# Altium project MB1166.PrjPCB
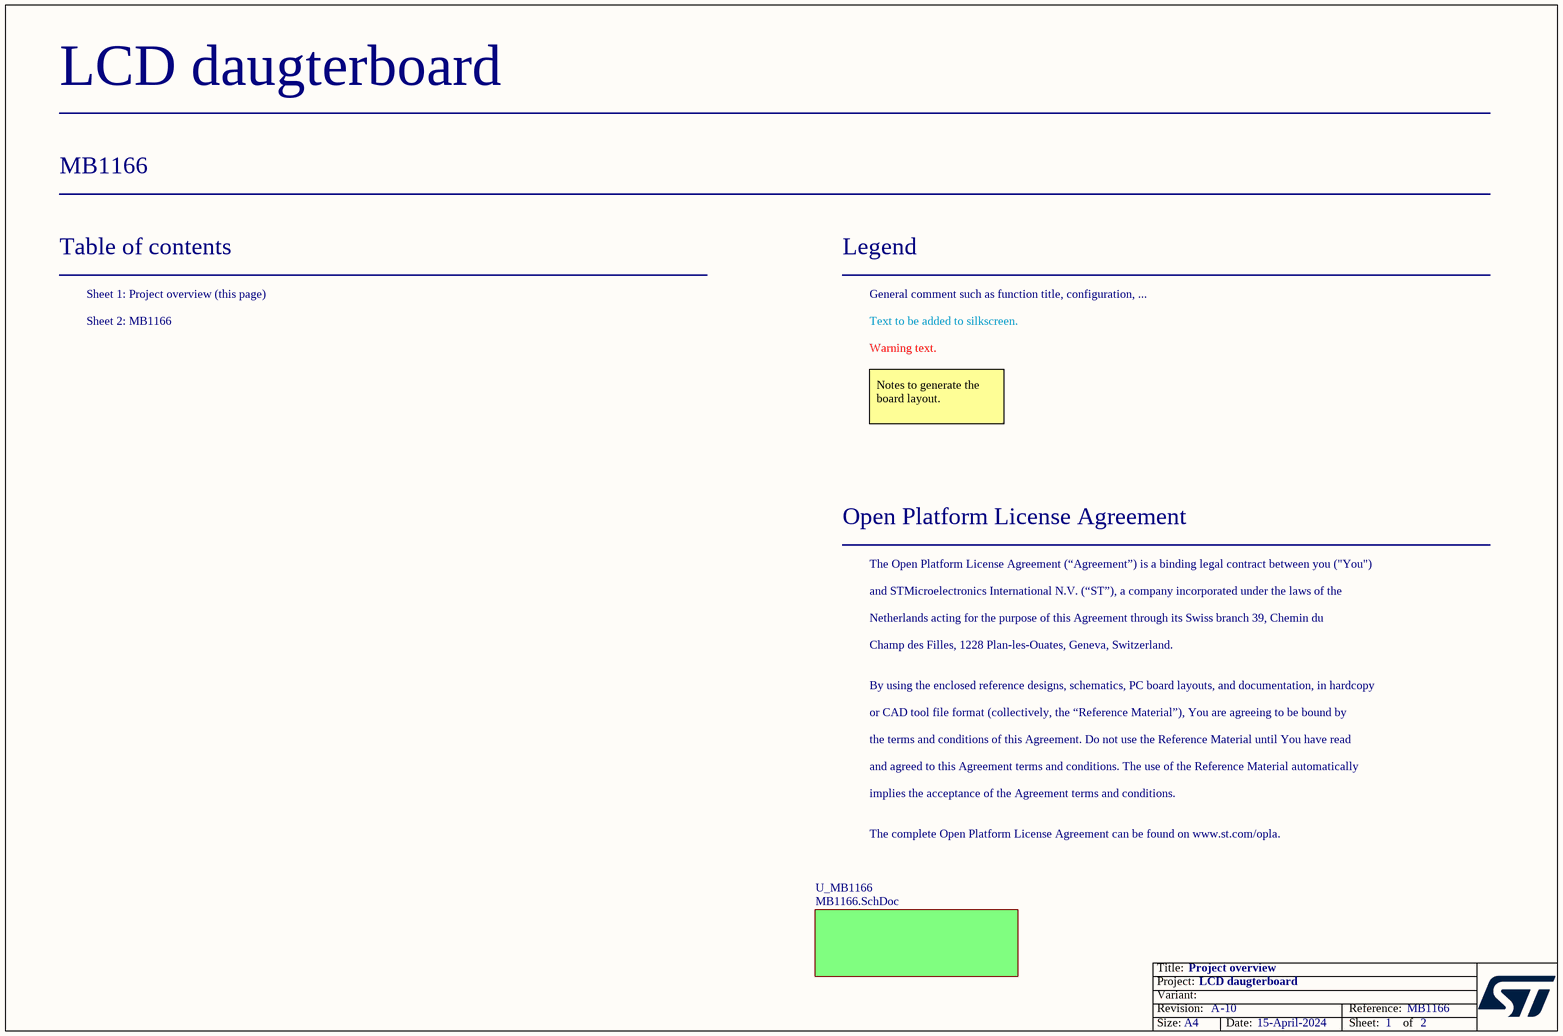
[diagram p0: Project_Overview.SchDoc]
Board_reference: MB1166; Board_PCB_revision: A; Board_name: LCD daugterboard; Board_document_date: 15-April-2024; Board_Assembly_revision: 10
2 sheets, 35 parts. Net scope: global (net labels, ports and power ports of the same name join across sheets).
Sheets:
  Project_Overview.SchDoc
    U_MB1166 = MB1166.SchDoc

## Sheet Project_Overview.SchDoc: Project overview
size A4; Date: Not used; ApprovedBy: Not used; CheckedBy: Not used; Author: Not used; CompanyName: STMicroelectronics; DrawnBy: Not used; Engineer: Not used; Organization: Not used; Address1: Not used; Address2: Not used; Address3: Not used; Address4: Not used; DocumentNumber: MB1166; Revision: Not used; SheetNumber: 1; SheetTotal: 2

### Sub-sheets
U_MB1166 = MB1166.SchDoc: no entries

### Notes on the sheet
- Table of contents
- Sheet 1: Project overview (this page)
- Legend
- General comment such as function title, configuration, ...
- Sheet 2: MB1166
- Text to be added to silkscreen.
- Warning text.
- Notes to generate the board layout.
- Open Platform License Agreement
- The Open Platform License Agreement (“Agreement”) is a binding legal contract between you ("You")
- and STMicroelectronics International N.V. (“ST”), a company incorporated under the laws of the
- Netherlands acting for the purpose of this Agreement through its Swiss branch 39, Chemin du
- Champ des Filles, 1228 Plan-les-Ouates, Geneva, Switzerland.
- By using the enclosed reference designs, schematics, PC board layouts, and documentation, in hardcopy
- or CAD tool file format (collectively, the “Reference Material”), You are agreeing to be bound by
- the terms and conditions of this Agreement. Do not use the Reference Material until You have read
- and agreed to this Agreement terms and conditions. The use of the Reference Material automatically
- implies the acceptance of the Agreement terms and conditions.
- The complete Open Platform License Agreement can be found on www.st.com/opla.

## Sheet MB1166.SchDoc: 4 inch DSI LCD board
size A4; DocumentNumber: MB1166; Revision: A.1; SheetNumber: 2; SheetTotal: 2; Project: LCD daugterboard
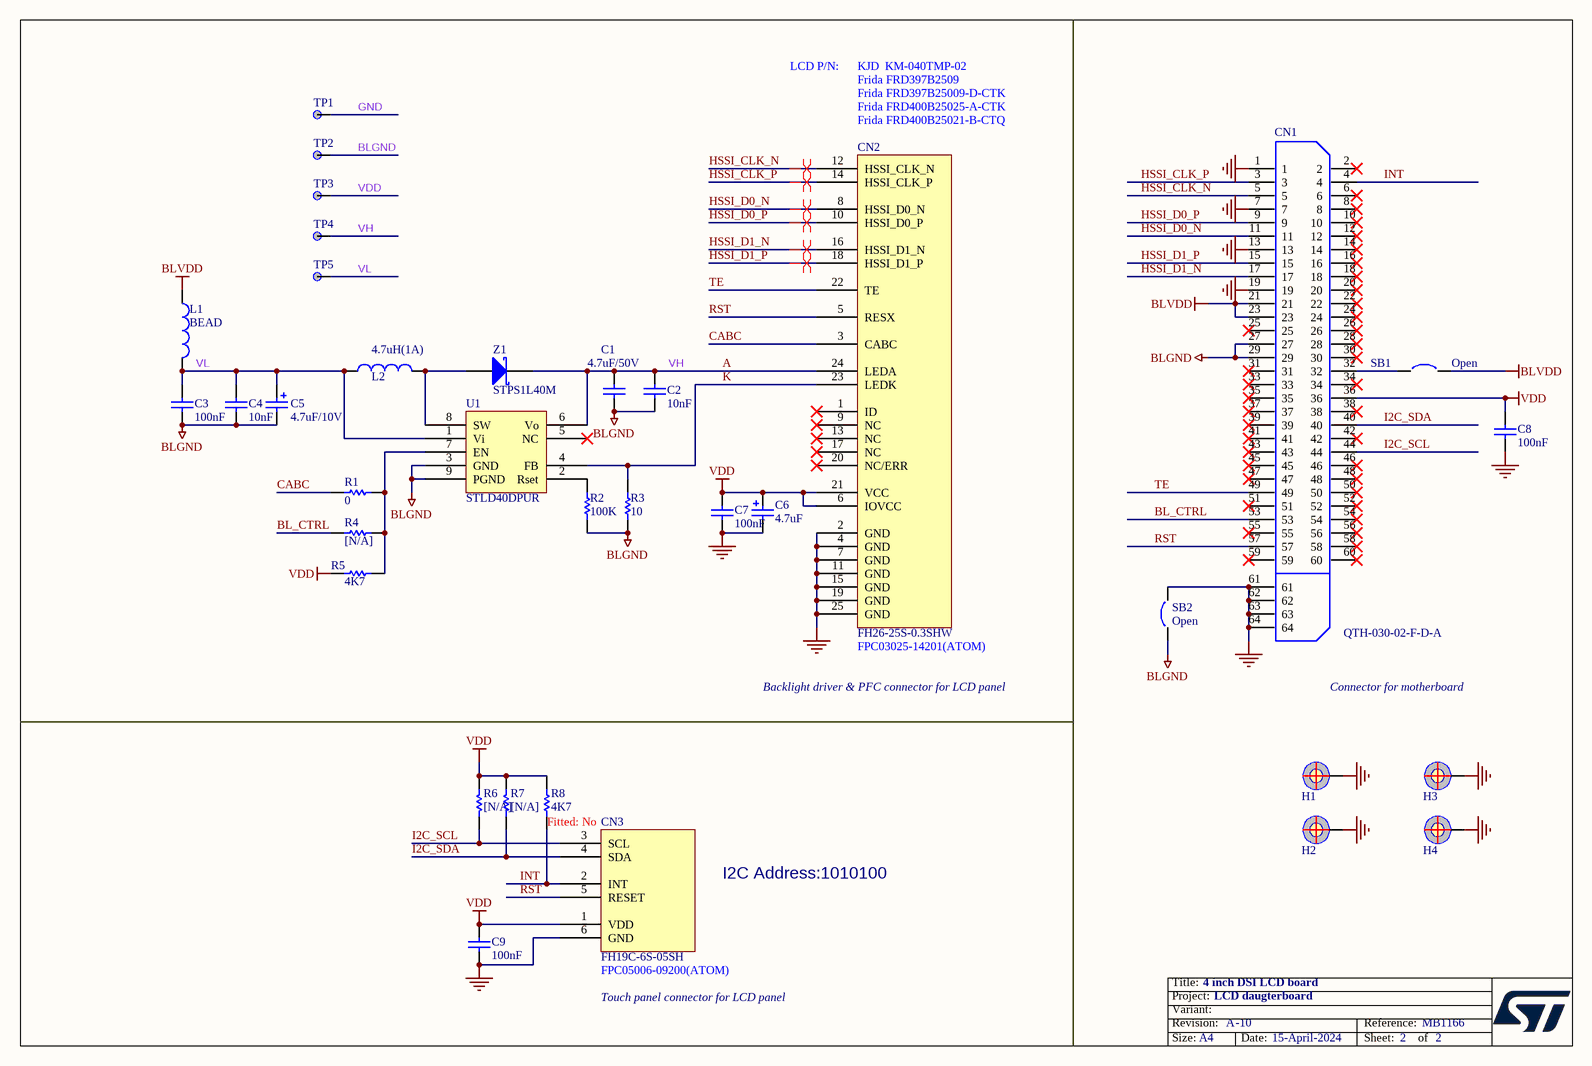
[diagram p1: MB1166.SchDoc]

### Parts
C1  4.7uF/50V  [1206C]
C2  10nF  [0603C]
C3  100nF  [0603C]
C4  10nF  [0603C]
C5  4.7uF/10V  [1206C]
C6  4.7uF  [TAN-A]
C7  100nF  [0603C]
C8  100nF  [0603C]
C9  100nF  [0603C]
CN1  QTH-030-02-F-D-A  [QTH-030-02-F-D-A]
CN2  FH26-25S-0.3SHW  [FPC25_FPC03025-1420]
CN3  FH19C-6S-05SH  [FH19C-6S-0R5Sh_FPC_CPT]
H1  POSITION HOLE  [HOLE_C9D4R5]  (value not drawn)
H2  POSITION HOLE  [HOLE_C9D4R5]  (value not drawn)
H3  POSITION HOLE  [HOLE_C9D4R5]  (value not drawn)
H4  POSITION HOLE  [HOLE_C9D4R5]  (value not drawn)
L1  BEAD  [0603L]
L2  4.7uH(1A)  [1210L]
R1  0  [0603R]
R2  100K  [0603R]
R3  10  [0603R]
R4  [N/A]  [0603R]
R5  4K7  [0603R]
R6  [N/A]  [0603R]
R7  [N/A]  [0603R]
R8  4K7  Fitted: No  [0603R]
SB1  Open  [SB_0603]
SB2  Open  [SB_0603]
TP1  (no value)  [TP]
TP2  (no value)  [TP]
TP3  (no value)  [TP]
TP4  (no value)  [TP]
TP5  (no value)  [TP]
U1  STLD40DPUR  [SON8_0R65_3X3]
Z1  STPS1L40M  [DO-216AA]

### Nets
BLGND: C1.2 C2.1 C3.1 C4.1 C5.2 CN1.27 CN1.29 R2.2 R3.1 SB2.1 TP2.1 U1.3(GND) U1.9(PGND)
BLVDD: CN1.21 CN1.23 L1.1 SB1.2
GND: C6.2 C7.1 C8.1 C9.1 CN1.1 CN1.7 CN1.13 CN1.19 CN1.61 CN1.62 CN1.63 CN1.64 CN2.2(GND) CN2.4(GND) CN2.7(GND) CN2.11(GND) CN2.15(GND) CN2.19(GND) CN2.25(GND) CN3.6(GND) H1.1 H2.1 H3.1 H4.1 SB2.2 TP1.1
VDD: C6.1 C7.2 C8.2 C9.2 CN1.36 CN2.6(IOVCC) CN2.21(VCC) CN3.1(VDD) R5.2 R6.2 R7.2 R8.1 TP3.1
A: C1.1 C2.2 CN2.24(LEDA) TP4.1 U1.6(Vo) Z1.2(K)  [also labelled VH]
BL_CTRL: CN1.53 R4.2
CABC: CN2.3(CABC) R1.2
HSSI_CLK_N: CN1.5 CN2.12(HSSI_CLK_N)
HSSI_CLK_P: CN1.3 CN2.14(HSSI_CLK_P)
HSSI_D0_N: CN1.11 CN2.8(HSSI_D0_N)
HSSI_D0_P: CN1.9 CN2.10(HSSI_D0_P)
HSSI_D1_N: CN1.17 CN2.16(HSSI_D1_N)
HSSI_D1_P: CN1.15 CN2.18(HSSI_D1_P)
I2C_SCL: CN1.44 CN3.3(SCL) R6.1
I2C_SDA: CN1.40 CN3.4(SDA) R7.1
INT: CN1.4 CN3.2(INT) R8.2
K: CN2.23(LEDK) R3.2 U1.4(FB)
RST: CN1.57 CN2.5(RESX) CN3.5(RESET)
TE: CN1.49 CN2.22(TE)
VL: C3.2 C4.2 C5.1 L1.2 L2.1 TP5.1 U1.1(Vi)
NetCN1_32: CN1.32 SB1.1
NetL2_2: L2.2 U1.8(SW) Z1.1(A)
NetR1_1: R1.1 R4.1 R5.1 U1.7(EN)
NetR2_1: R2.1 U1.2(Rset)

Not connected (* = marked no-connect by the designer): CN1 2* 6* 8* 10* 12* 14* 16* 18* 20* 22* 24* 25* 26* 28* 30* 31* 33* 34* 35* 37* 38* 39* 41* 42* 43* 45* 46* 47* 48* 50* 51* 52* 54* 55* 56* 58* 59* 60*; CN2 1(ID)* 9(NC)* 13(NC)* 17(NC)* 20(NC/ERR)*; U1 5(NC)*

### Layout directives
differential pair: HSSI_CLK_N, HSSI_CLK_P, HSSI_D0_N, HSSI_D0_P, HSSI_D1_N, HSSI_D1_P

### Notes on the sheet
- LCD P/N:
- KJD  KM-040TMP-02
- Frida FRD397B2509
- Frida FRD397B25009-D-CTK
- Frida FRD400B25025-A-CTK
- (near CN2) Frida FRD400B25021-B-CTQ
- (near CN2) FPC03025-14201(ATOM)
- Backlight driver & PFC connector for LCD panel
- Connector for motherboard
- I2C Address:1010100
- Touch panel connector for LCD panel
- (near CN3) FPC05006-09200(ATOM)

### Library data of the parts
C1-C4 C7-C9 = CAP: Capacitor; Value: 100pF
C5 C6 = Cap Pol1: Polarized Capacitor (Radial); Value: 100pF
CN1 = QTH-030-02-F-D-A: HIGH SPEED TERMINAL STRIP, .5mm PITCH, 60 PINS.; MANUFACTURER: SAMTEC; PCB DECAL: QTH-030-02-X-D-A
L1 L2 = Inductor: Value: 100uH
R1-R8 = Res1: Resistor; Value: 1K
SB1 SB2 = Circuit Breaker
TP1-TP5 = TP
U1 = STLD40DPMR
Z1 = D Schottky: Schottky Diode; Code - JEDEC: DO-214-AA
